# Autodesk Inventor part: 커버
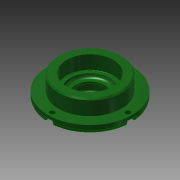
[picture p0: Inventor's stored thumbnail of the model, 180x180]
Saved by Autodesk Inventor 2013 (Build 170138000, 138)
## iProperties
Company: 한국ATC센터
Created: 2016-04
Part Number: 커버
Document SubType Name: Modeling
Designer: mdu
Density: 7.86 g/cm^3
Mass: 351.567 g
Surface Area: 161.165 cm^2
Volume: 44.7286 cm^3
Material: 강철, 연강
Author: mdu
Revision Number: 1
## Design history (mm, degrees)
sketch "스케치1"
  geometry: C1 r 36 at (0, 0); 1 further point
  constraints: 1 centre point, 1 coincident
  dimensions: "d0" = 72 diameter of C1
extrude "돌출1" new body sketch "스케치1" distance "d1" = 7; taper "d2" = 0 deg
sketch "스케치2"
  geometry: C1 r 27 at (0, 0); 1 further point
  constraints: 1 centre point, 1 coincident
  dimensions: "d3" = 54 diameter of C1
extrude "돌출2" join sketch "스케치2" distance "d4" = 13; taper "d5" = 0 deg
sketch "스케치3"
  geometry: C1 r 20 at (0, 0); 1 further point
  constraints: 1 centre point, 1 coincident
  dimensions: "d6" = 40 diameter of C1
extrude "돌출3" join sketch "스케치3" distance "d7" = 5; taper "d8" = 0 deg
hole "구멍1" diameter "d11" = 25; stored, may be unused: countersink angle "d15" = 90 deg, drill point angle "d17" = 118 deg; dims "d9" = 10, "d10" = 10, "d12" = 6, "d13" = 32, "d14" = 8.3, "d16" = 8
hole "구멍2" diameter "d20" = 34; stored, may be unused: countersink angle "d24" = 90 deg, drill point angle "d26" = 0 deg; dims "d18" = 10, "d19" = 10, "d21" = 6, "d22" = 40, "d23" = 12, "d25" = 3
fillet "모깎기2" dims "d34" = 3
fillet "모깎기1" dims "d27" = 0.3
chamfer "모따기1" distance "d28" = 1; stored, may be unused: second distance "d29" = 2, angle "d30" = 45 deg
chamfer "모따기2" distance "d31" = 1.2; stored, may be unused: second distance "d32" = 2, angle "d33" = 30 deg
sketch "스케치4" dims "d35" = 65
  geometry: 3 further points
  constraints: 2 horizontal alignment, 1 coincident, 2 other
hole "구멍3" sketch "스케치4" at (32.5, 0) diameter "d36" = 4.5; stored, may be unused: countersink angle "d40" = 90 deg, drill point angle "d42" = 118 deg; dims "d37" = 6, "d38" = 8, "d39" = 4.4, "d41" = 13
sketch "스케치5"
  geometry: L1 (4, 0)-(4, 3.5); L2 (-4, 3.5)-(-4, 0); L3 (4, 3.5)-(-4, 3.5); C1 r 2.25 at (0, 0) reference; C2 r 36 at (0, -32.5) reference; A1 r 4 centre (0, 0) between (-2.037, 3.442) and (2.037, 3.442) reference; A2 r 36 centre (0, -32.5) between (2.037, 3.442) and (-2.037, 3.442) reference; 2 further points
  constraints: 6 end point, 2 horizontal alignment, 2 point on circle, 1 horizontal, 1 midpoint, 1 parallel, 1 tangent, 1 vertical, 1 vertical alignment
extrude "돌출4" cut sketch "스케치5" stored distance "d47" = 24.5; taper "d48" = 0 deg
node "솔리드1"
pattern_circular "원형 패턴1" dims angle "d44" = 360 deg
pattern_circular "원형 패턴2" dims angle "d50" = 360 deg
node "투영된 루프1"
